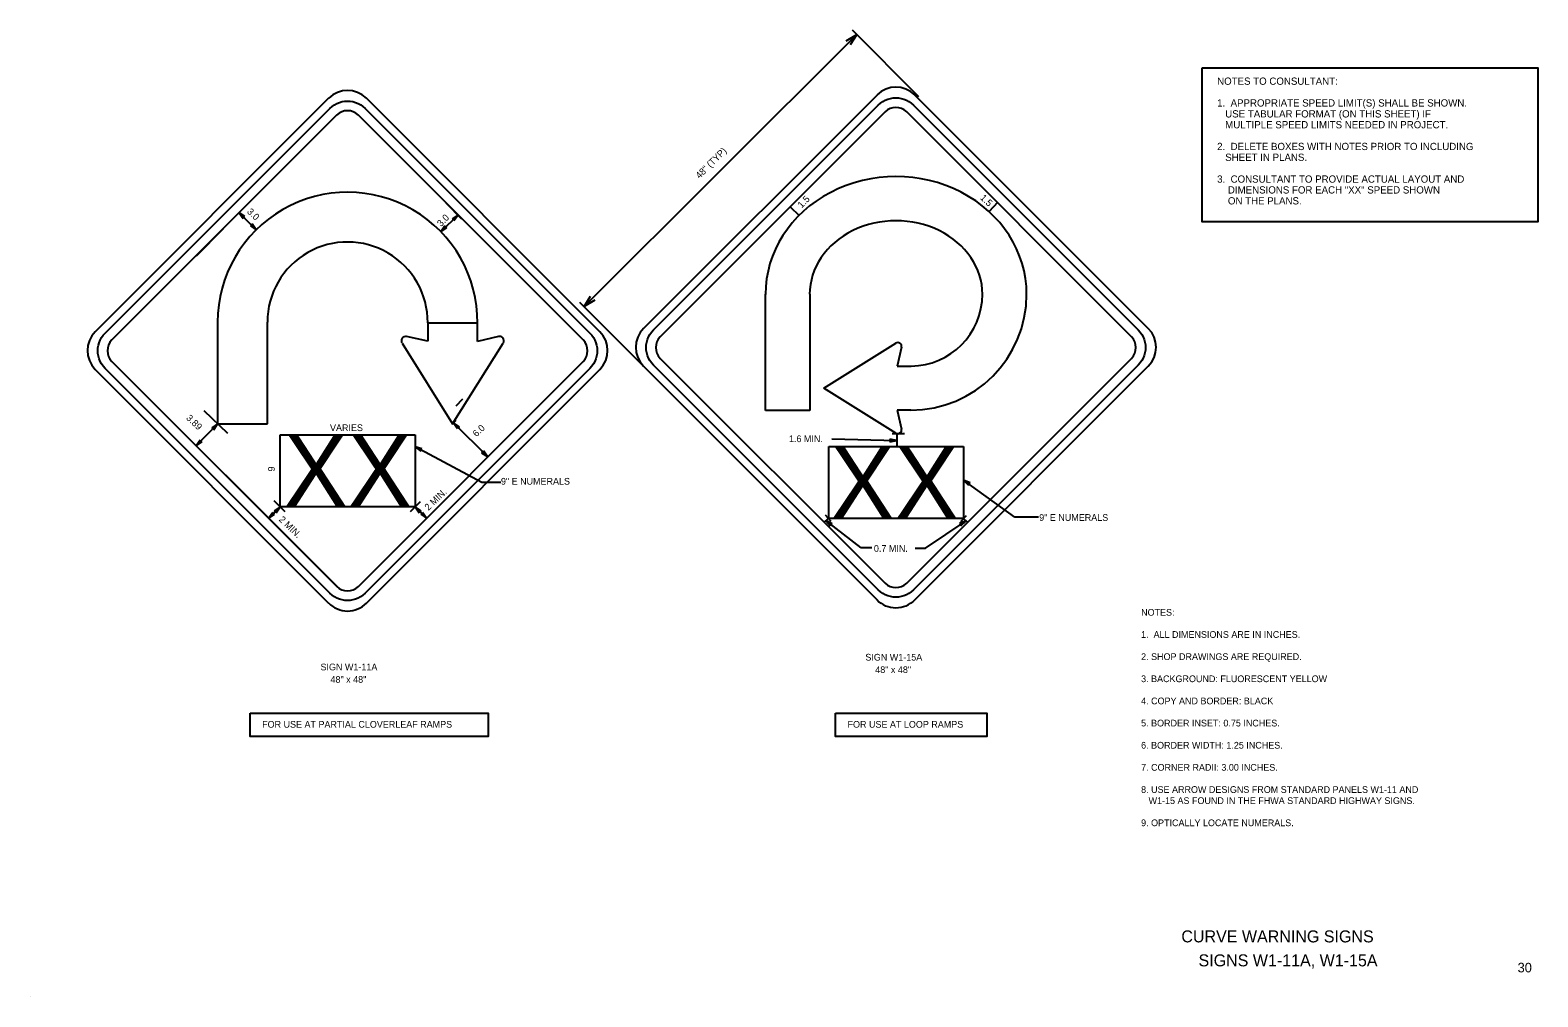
# Model space of a CAD drawing. Extents: x 5257.5 to 5273.2, y 918.1 to 928.2.
import ezdxf

# ---------------------------------------------------------------- set-up
doc = ezdxf.new("R2010")
doc.units = 0
for name, color, linetype in [('AdhocPoint_dp', 7, 'Continuous'), ('GSDims', 7, 'Continuous'), ('SignPanel', 7, 'Continuous'), ('TextAlert', 7, 'Continuous'), ('TextDetails', 7, 'Continuous'), ('TextLabel', 7, 'Continuous'), ('TextMisc', 7, 'Continuous'), ('TextNotes', 7, 'Continuous'), ('TextShtNo', 7, 'Continuous')]:
    doc.layers.add(name, color=color, linetype=linetype)

msp = doc.modelspace()

# ---------------------------------------------------------------- linework, layer by layer
at = {"layer": 'AdhocPoint_dp'}
msp.add_line((5257.494, 918.075), (5257.494, 918.075), dxfattribs=at)
at = {"layer": 'GSDims'}
for p, q in [((5259.852, 926.075), (5259.674, 926.253)), ((5259.674, 926.253), (5259.716, 926.192)), ((5259.735, 926.212), (5259.674, 926.253)), ((5261.829, 926.357), (5261.995, 926.19)), ((5265.422, 926.315), (5265.514, 926.223)), ((5267.584, 926.358), (5267.497, 926.264)), ((5259.716, 926.192), (5259.722, 926.206)), ((5259.722, 926.206), (5259.735, 926.212)), ((5259.805, 926.123), (5259.792, 926.117)), ((5259.792, 926.117), (5259.852, 926.075)), ((5259.811, 926.136), (5259.805, 926.123)), ((5259.852, 926.075), (5259.811, 926.136)), ((5261.958, 926.23), (5261.777, 926.055)), ((5261.82, 926.115), (5261.777, 926.055)), ((5261.777, 926.055), (5261.839, 926.095)), ((5261.825, 926.102), (5261.82, 926.115)), ((5261.839, 926.095), (5261.825, 926.102)), ((5261.958, 926.23), (5261.896, 926.19)), ((5261.896, 926.19), (5261.91, 926.184)), ((5261.91, 926.184), (5261.915, 926.17)), ((5261.915, 926.17), (5261.958, 926.23)), ((5259.227, 923.82), (5259.45, 924.052)), ((5259.555, 923.951), (5259.31, 924.187)), ((5259.45, 924.052), (5259.39, 924.009)), ((5259.41, 923.99), (5259.45, 924.052)), ((5261.895, 924.047), (5261.937, 924.09)), ((5261.9, 924.052), (5261.904, 924.049)), ((5261.91, 924.062), (5262.263, 923.709)), ((5261.91, 924.062), (5261.951, 924.001)), ((5261.971, 924.02), (5261.91, 924.062)), ((5259.268, 923.882), (5259.227, 923.82)), ((5259.274, 923.868), (5259.268, 923.882)), ((5259.39, 924.009), (5259.404, 924.004)), ((5259.404, 924.004), (5259.41, 923.99)), ((5260.103, 923.186), (5260.103, 923.936)), ((5260.103, 923.936), (5261.511, 923.936)), ((5261.511, 923.936), (5261.511, 923.186)), ((5261.951, 924.001), (5261.957, 924.014)), ((5261.957, 924.014), (5261.971, 924.02)), ((5265.856, 923.894), (5266.534, 923.876)), ((5266.534, 923.876), (5266.461, 923.892)), ((5266.461, 923.892), (5266.467, 923.878)), ((5266.613, 923.948), (5266.487, 923.948)), ((5266.534, 923.948), (5266.534, 923.813)), ((5259.227, 923.82), (5259.288, 923.863)), ((5259.288, 923.863), (5259.274, 923.868)), ((5262.206, 923.44), (5261.511, 923.812)), ((5261.511, 923.812), (5261.568, 923.765)), ((5261.581, 923.789), (5261.511, 923.812)), ((5261.568, 923.765), (5261.57, 923.78)), ((5261.57, 923.78), (5261.581, 923.789)), ((5262.216, 923.756), (5262.202, 923.75)), ((5262.202, 923.75), (5262.263, 923.709)), ((5262.222, 923.77), (5262.216, 923.756)), ((5262.263, 923.709), (5262.222, 923.77)), ((5265.824, 923.063), (5265.824, 923.813)), ((5265.824, 923.813), (5267.231, 923.813)), ((5266.467, 923.878), (5266.461, 923.864)), ((5266.461, 923.864), (5266.534, 923.876)), ((5267.231, 923.813), (5267.231, 923.063)), ((5262.404, 923.44), (5262.206, 923.44)), ((5267.766, 923.078), (5267.231, 923.465)), ((5267.231, 923.465), (5267.282, 923.412)), ((5267.298, 923.434), (5267.231, 923.465)), ((5267.282, 923.412), (5267.286, 923.426)), ((5267.286, 923.426), (5267.298, 923.434)), ((5260.024, 923.126), (5259.982, 923.065)), ((5259.982, 923.065), (5260.044, 923.106)), ((5259.983, 923.065), (5260.102, 923.184)), ((5260.03, 923.112), (5260.024, 923.126)), ((5260.044, 923.106), (5260.03, 923.112)), ((5260.154, 923.132), (5260.038, 923.248)), ((5260.102, 923.184), (5260.041, 923.143)), ((5260.041, 923.143), (5260.054, 923.137)), ((5260.054, 923.137), (5260.06, 923.123)), ((5260.06, 923.123), (5260.102, 923.184)), ((5261.511, 923.186), (5260.103, 923.186)), ((5261.463, 923.136), (5261.566, 923.24)), ((5261.629, 923.067), (5261.511, 923.185)), ((5261.511, 923.185), (5261.553, 923.124)), ((5261.572, 923.143), (5261.511, 923.185)), ((5261.553, 923.124), (5261.559, 923.138)), ((5261.559, 923.138), (5261.572, 923.143)), ((5261.582, 923.115), (5261.568, 923.109)), ((5261.568, 923.109), (5261.629, 923.067)), ((5261.588, 923.128), (5261.582, 923.115)), ((5261.629, 923.067), (5261.588, 923.128)), ((5265.851, 923.034), (5265.79, 923.099)), ((5265.775, 923.025), (5265.82, 923.067)), ((5266.163, 922.758), (5265.794, 923.043)), ((5265.794, 923.043), (5265.843, 922.987)), ((5265.86, 923.009), (5265.794, 923.043)), ((5267.231, 923.063), (5265.824, 923.063)), ((5265.843, 922.987), (5265.847, 923.002)), ((5265.847, 923.002), (5265.86, 923.009)), ((5266.834, 922.755), (5267.256, 923.039)), ((5267.256, 923.039), (5267.188, 923.01)), ((5267.188, 923.01), (5267.2, 923.002)), ((5267.2, 923.002), (5267.203, 922.987)), ((5267.202, 923.033), (5267.262, 923.094)), ((5267.203, 922.987), (5267.256, 923.039)), ((5267.271, 923.024), (5267.231, 923.063)), ((5268.011, 923.078), (5267.766, 923.078)), ((5266.274, 922.758), (5266.163, 922.758)), ((5266.726, 922.755), (5266.834, 922.755))]:
    msp.add_line(p, q, dxfattribs=at)
at = {"layer": 'SignPanel'}
for p, q in [((5260.608, 927.446), (5258.173, 925.011)), ((5263.437, 925.011), (5261.001, 927.446)), ((5266.328, 927.48), (5263.892, 925.045)), ((5266.493, 927.348), (5266.464, 927.34)), ((5266.524, 927.351), (5266.493, 927.348)), ((5266.554, 927.348), (5266.524, 927.351)), ((5266.584, 927.339), (5266.554, 927.348)), ((5269.156, 925.045), (5266.721, 927.48)), ((5266.411, 927.304), (5264.067, 924.96)), ((5266.436, 927.325), (5266.411, 927.304)), ((5266.464, 927.34), (5266.436, 927.325)), ((5266.612, 927.325), (5266.584, 927.339)), ((5266.637, 927.304), (5266.612, 927.325)), ((5268.981, 924.96), (5266.637, 927.304)), ((5259.228, 925.804), (5259.511, 926.087)), ((5265.165, 924.191), (5265.165, 925.402)), ((5265.626, 925.402), (5265.626, 924.191)), ((5259.45, 925.111), (5259.45, 924.052)), ((5259.969, 924.052), (5259.969, 925.111)), ((5261.641, 925.103), (5262.16, 925.102)), ((5262.16, 925.102), (5261.641, 925.103)), ((5261.641, 925.103), (5261.641, 924.912)), ((5262.16, 924.955), (5262.16, 925.102)), ((5261.373, 924.894), (5261.9, 924.052)), ((5261.641, 924.912), (5261.421, 924.962)), ((5261.9, 924.052), (5262.428, 924.894)), ((5262.379, 924.962), (5262.16, 924.91)), ((5262.16, 924.91), (5262.16, 924.955)), ((5264.023, 924.878), (5264.02, 924.847)), ((5264.02, 924.847), (5264.023, 924.816)), ((5264.032, 924.907), (5264.023, 924.878)), ((5264.046, 924.935), (5264.032, 924.907)), ((5264.067, 924.96), (5264.046, 924.935)), ((5265.774, 924.423), (5266.523, 924.892)), ((5266.583, 924.849), (5266.537, 924.653)), ((5269.002, 924.935), (5268.981, 924.96)), ((5269.017, 924.907), (5269.002, 924.935)), ((5269.025, 924.878), (5269.017, 924.907)), ((5269.028, 924.847), (5269.025, 924.878)), ((5269.025, 924.816), (5269.028, 924.847)), ((5260.717, 922.335), (5258.347, 924.7)), ((5260.918, 922.356), (5263.262, 924.7)), ((5264.023, 924.816), (5264.032, 924.787)), ((5264.032, 924.787), (5264.046, 924.759)), ((5264.046, 924.759), (5264.067, 924.734)), ((5264.067, 924.734), (5266.411, 922.39)), ((5266.637, 922.39), (5268.981, 924.734)), ((5268.981, 924.734), (5269.002, 924.759)), ((5269.002, 924.759), (5269.017, 924.787)), ((5269.017, 924.787), (5269.025, 924.816)), ((5258.173, 924.618), (5260.608, 922.18)), ((5261.002, 922.18), (5263.437, 924.618)), ((5263.892, 924.652), (5266.328, 922.214)), ((5266.537, 924.653), (5266.682, 924.653)), ((5266.721, 922.214), (5269.156, 924.652)), ((5266.523, 923.954), (5265.774, 924.423)), ((5261.937, 924.238), (5262.008, 924.311)), ((5259.45, 924.052), (5259.969, 924.052)), ((5265.626, 924.191), (5265.165, 924.191)), ((5266.679, 924.192), (5266.538, 924.192)), ((5266.538, 924.192), (5266.583, 923.997)), ((5266.411, 922.39), (5266.436, 922.369)), ((5266.436, 922.369), (5266.464, 922.354)), ((5266.464, 922.354), (5266.493, 922.346)), ((5266.493, 922.346), (5266.524, 922.343)), ((5266.524, 922.343), (5266.554, 922.346)), ((5266.554, 922.346), (5266.584, 922.355)), ((5266.584, 922.355), (5266.612, 922.369)), ((5266.612, 922.369), (5266.637, 922.39))]:
    msp.add_line(p, q, dxfattribs=at)
for points in [[(5263.332, 924.629), (5260.988, 922.285), (5260.966, 922.265), (5260.941, 922.248), (5260.916, 922.234), (5260.889, 922.223), (5260.861, 922.215), (5260.833, 922.21), (5260.805, 922.209), (5260.776, 922.21), (5260.748, 922.215), (5260.72, 922.223), (5260.693, 922.234), (5260.668, 922.248), (5260.643, 922.265), (5260.621, 922.285), (5258.277, 924.629), (5258.256, 924.652), (5258.239, 924.676), (5258.225, 924.702), (5258.214, 924.729), (5258.206, 924.756), (5258.202, 924.785), (5258.2, 924.813), (5258.202, 924.842), (5258.206, 924.87), (5258.214, 924.897), (5258.225, 924.924), (5258.239, 924.95), (5258.256, 924.974), (5258.277, 924.997), (5258.277, 924.997), (5260.621, 927.341), (5260.643, 927.361), (5260.668, 927.379), (5260.693, 927.392), (5260.72, 927.403), (5260.748, 927.411), (5260.776, 927.416), (5260.805, 927.417), (5260.833, 927.416), (5260.861, 927.411), (5260.889, 927.403), (5260.916, 927.392), (5260.942, 927.378), (5260.966, 927.361), (5260.989, 927.341), (5260.989, 927.341), (5263.332, 924.997), (5263.353, 924.974), (5263.37, 924.95), (5263.384, 924.924), (5263.395, 924.897), (5263.402, 924.87), (5263.407, 924.842), (5263.409, 924.813), (5263.407, 924.785), (5263.402, 924.756), (5263.395, 924.729), (5263.384, 924.702), (5263.37, 924.676), (5263.353, 924.652)], [(5269.052, 924.663), (5266.708, 922.319), (5266.685, 922.299), (5266.661, 922.282), (5266.635, 922.268), (5266.608, 922.257), (5266.581, 922.249), (5266.553, 922.244), (5266.524, 922.243), (5266.495, 922.244), (5266.467, 922.249), (5266.44, 922.257), (5266.413, 922.268), (5266.387, 922.282), (5266.363, 922.299), (5266.34, 922.319), (5263.996, 924.663), (5263.976, 924.686), (5263.959, 924.71), (5263.945, 924.736), (5263.934, 924.762), (5263.926, 924.79), (5263.921, 924.818), (5263.92, 924.847), (5263.921, 924.876), (5263.926, 924.904), (5263.934, 924.931), (5263.945, 924.958), (5263.959, 924.984), (5263.976, 925.008), (5263.996, 925.031), (5263.996, 925.031), (5266.34, 927.375), (5266.363, 927.395), (5266.387, 927.413), (5266.413, 927.426), (5266.44, 927.437), (5266.467, 927.445), (5266.495, 927.45), (5266.524, 927.451), (5266.553, 927.45), (5266.581, 927.445), (5266.608, 927.437), (5266.635, 927.426), (5266.661, 927.412), (5266.685, 927.395), (5266.708, 927.375), (5266.708, 927.375), (5269.052, 925.031), (5269.072, 925.008), (5269.089, 924.984), (5269.103, 924.958), (5269.114, 924.931), (5269.122, 924.904), (5269.127, 924.876), (5269.128, 924.847), (5269.127, 924.818), (5269.122, 924.79), (5269.114, 924.763), (5269.103, 924.736), (5269.089, 924.71), (5269.072, 924.686)], [(5263.262, 924.7), (5263.282, 924.725), (5263.297, 924.753), (5263.306, 924.782), (5263.309, 924.813), (5263.306, 924.844), (5263.297, 924.873), (5263.282, 924.901), (5263.262, 924.926), (5260.918, 927.271), (5260.893, 927.291), (5260.865, 927.305), (5260.835, 927.314), (5260.805, 927.317), (5260.774, 927.315), (5260.744, 927.306), (5260.717, 927.291), (5260.691, 927.271), (5258.347, 924.926), (5258.327, 924.901), (5258.312, 924.873), (5258.303, 924.844), (5258.3, 924.813), (5258.303, 924.782), (5258.312, 924.753), (5258.327, 924.725), (5258.347, 924.7), (5260.692, 922.356), (5260.717, 922.335), (5260.744, 922.321), (5260.774, 922.312), (5260.805, 922.309), (5260.835, 922.312), (5260.865, 922.321), (5260.893, 922.335), (5260.918, 922.356)]]:
    msp.add_lwpolyline(points, close=True, dxfattribs=at)
for centre, radius, start, end in [((5260.805, 927.25), 0.278, 45.0014, 134.9986), ((5266.524, 927.284), 0.278, 45.0014, 134.9986), ((5260.805, 925.111), 1.355, 359.6222, 180), ((5260.805, 925.111), 0.836, 359.4582, 180), ((5266.678, 925.403), 1.21, 270.0527, 360), ((5266.678, 925.403), 0.749, 270.3218, 0), ((5258.37, 924.815), 0.278, 134.9986, 224.9689), ((5263.24, 924.815), 0.278, 315.0311, 45.0014), ((5264.089, 924.849), 0.278, 134.9986, 224.9689), ((5268.96, 924.849), 0.278, 315.0311, 45.0014), ((5261.411, 924.918), 0.045, 77.1592, 212.0582), ((5262.39, 924.918), 0.045, 327.9418, 103.258), ((5260.805, 922.377), 0.278, 224.9689, 315.0311), ((5266.524, 922.411), 0.278, 224.9689, 315.0311)]:
    msp.add_arc(centre, radius, start, end, dxfattribs=at)
for centre, major_axis, ratio, start_param, end_param in [((5266.526, 925.402), (1.362, 0.001), 0.90173, 0, 3.141593), ((5266.526, 925.402), (0.901, 0), 0.851426, 0, 3.141593), ((5266.544, 924.858), (0.04, 0), 0.999992, 6.05179, 8.413502), ((5266.544, 923.988), (0.04, 0), 0.999992, 4.152868, 6.5073)]:
    msp.add_ellipse(centre, major_axis=major_axis, ratio=ratio, start_param=start_param, end_param=end_param, dxfattribs=at)
at = {"layer": 'TextAlert'}
msp.add_lwpolyline([(5269.72, 927.763), (5273.22, 927.763), (5273.22, 926.157), (5269.72, 926.157)], close=True, dxfattribs=at)
at = {"layer": 'TextLabel'}
for points in [[(5259.788, 921.034), (5262.273, 921.034), (5262.273, 920.791), (5259.788, 920.791)], [(5265.895, 921.034), (5267.474, 921.034), (5267.474, 920.791), (5265.895, 920.791)]]:
    msp.add_lwpolyline(points, close=True, dxfattribs=at)
at = {"layer": 'TextShtNo'}
for p, q in [((5266.765, 927.463), (5266.071, 928.157)), ((5263.273, 925.273), (5266.116, 928.112)), ((5264.012, 924.532), (5263.228, 925.317))]:
    msp.add_line(p, q, dxfattribs=at)
for points in [[(5266.005, 928.046), (5266.116, 928.112), (5266.049, 928.002)], [(5263.383, 925.339), (5263.273, 925.273), (5263.339, 925.383)]]:
    msp.add_lwpolyline(points, dxfattribs=at)

# ---------------------------------------------------------------- texts
at = {"layer": 'GSDims'}
for s, rotation, p in [('1.5', 46.1868, (5265.542, 926.296)), ('1.5', 317.7111, (5267.397, 926.4)), ('3.0', 316.1868, (5259.751, 926.257)), ('3.0', 46.1868, (5261.781, 926.102)), ('3.89', 316.196, (5259.116, 924.105)), ('VARIES', 0.0084, (5260.622, 923.975)), ('6.0', 43.804, (5262.15, 923.91)), ('9', 91.196, (5260.046, 923.555)), ('2 MIN.', 43.804, (5261.648, 923.142)), ('2 MIN.', 316.196, (5260.083, 923.046))]:
    msp.add_text(s, height=0.07, rotation=rotation, dxfattribs=at).set_placement(p)
for s, p in [('1.6 MIN.', (5265.409, 923.86)), ('9" E NUMERALS', (5262.405, 923.417)), ('9" E NUMERALS', (5268.019, 923.039)), ('0.7 MIN.', (5266.295, 922.716))]:
    msp.add_text(s, height=0.07, dxfattribs=at).set_placement(p)
at = {"layer": 'SignPanel'}
for p in [(5260.14, 923.19), (5265.843, 923.063)]:
    msp.add_text('XX', height=0.7489, dxfattribs=at).set_placement(p)
at = {"layer": 'TextAlert'}
for s, p in [('NOTES TO CONSULTANT:', (5269.875, 927.587)), ('1.  APPROPRIATE SPEED LIMIT(S) SHALL BE SHOWN.', (5269.875, 927.36)), ('   USE TABULAR FORMAT (ON THIS SHEET) IF', (5269.875, 927.246)), ('   MULTIPLE SPEED LIMITS NEEDED IN PROJECT.', (5269.875, 927.133)), ('2.  DELETE BOXES WITH NOTES PRIOR TO INCLUDING', (5269.875, 926.906)), ('   SHEET IN PLANS.', (5269.875, 926.793)), ('3.  CONSULTANT TO PROVIDE ACTUAL LAYOUT AND', (5269.875, 926.566)), ('    ON THE PLANS. ', (5269.875, 926.339)), ('    DIMENSIONS FOR EACH "XX" SPEED SHOWN', (5269.875, 926.453))]:
    msp.add_text(s, height=0.0756, dxfattribs=at).set_placement(p)
at = {"layer": 'TextDetails'}
for s, p in [('SIGN W1-11A', (5260.523, 921.48)), ('SIGN W1-15A', (5266.206, 921.582)), ('48" x 48"', (5266.309, 921.452)), ('48" x 48"', (5260.627, 921.35))]:
    msp.add_text(s, height=0.07, dxfattribs=at).set_placement(p)
at = {"layer": 'TextLabel'}
for s, p in [('FOR USE AT PARTIAL CLOVERLEAF RAMPS', (5259.914, 920.882)), ('FOR USE AT LOOP RAMPS', (5266.02, 920.882))]:
    msp.add_text(s, height=0.07, dxfattribs=at).set_placement(p)
at = {"layer": 'TextMisc'}
for s, p in [('  CURVE WARNING SIGNS   ', (5269.409, 918.643)), ('  SIGNS W1-11A, W1-15A  ', (5269.588, 918.393))]:
    msp.add_text(s, height=0.125, rotation=360, dxfattribs=at).set_placement(p)
at = {"layer": 'TextNotes'}
for s, p in [('NOTES:', (5269.082, 922.05)), ('1.  ALL DIMENSIONS ARE IN INCHES.', (5269.082, 921.819)), ('2. SHOP DRAWINGS ARE REQUIRED.', (5269.082, 921.588)), ('3. BACKGROUND: FLUORESCENT YELLOW', (5269.082, 921.357)), ('4. COPY AND BORDER: BLACK', (5269.082, 921.126)), ('5. BORDER INSET: 0.75 INCHES.', (5269.082, 920.895)), ('6. BORDER WIDTH: 1.25 INCHES.', (5269.082, 920.664)), ('7. CORNER RADII: 3.00 INCHES.', (5269.082, 920.433)), ('8. USE ARROW DESIGNS FROM STANDARD PANELS W1-11 AND ', (5269.082, 920.202)), ('   W1-15 AS FOUND IN THE FHWA STANDARD HIGHWAY SIGNS.', (5269.082, 920.086)), ('9. OPTICALLY LOCATE NUMERALS.', (5269.082, 919.855))]:
    msp.add_text(s, height=0.07, dxfattribs=at).set_placement(p)
at = {"layer": 'TextShtNo'}
for s, height, rotation, p in [('48" (TYP)', 0.07, 44.9689, (5264.477, 926.603)), ('30', 0.1, 360, (5273.009, 918.33))]:
    msp.add_text(s, height=height, rotation=rotation, dxfattribs=at).set_placement(p)

doc.saveas('drawing.dxf')
